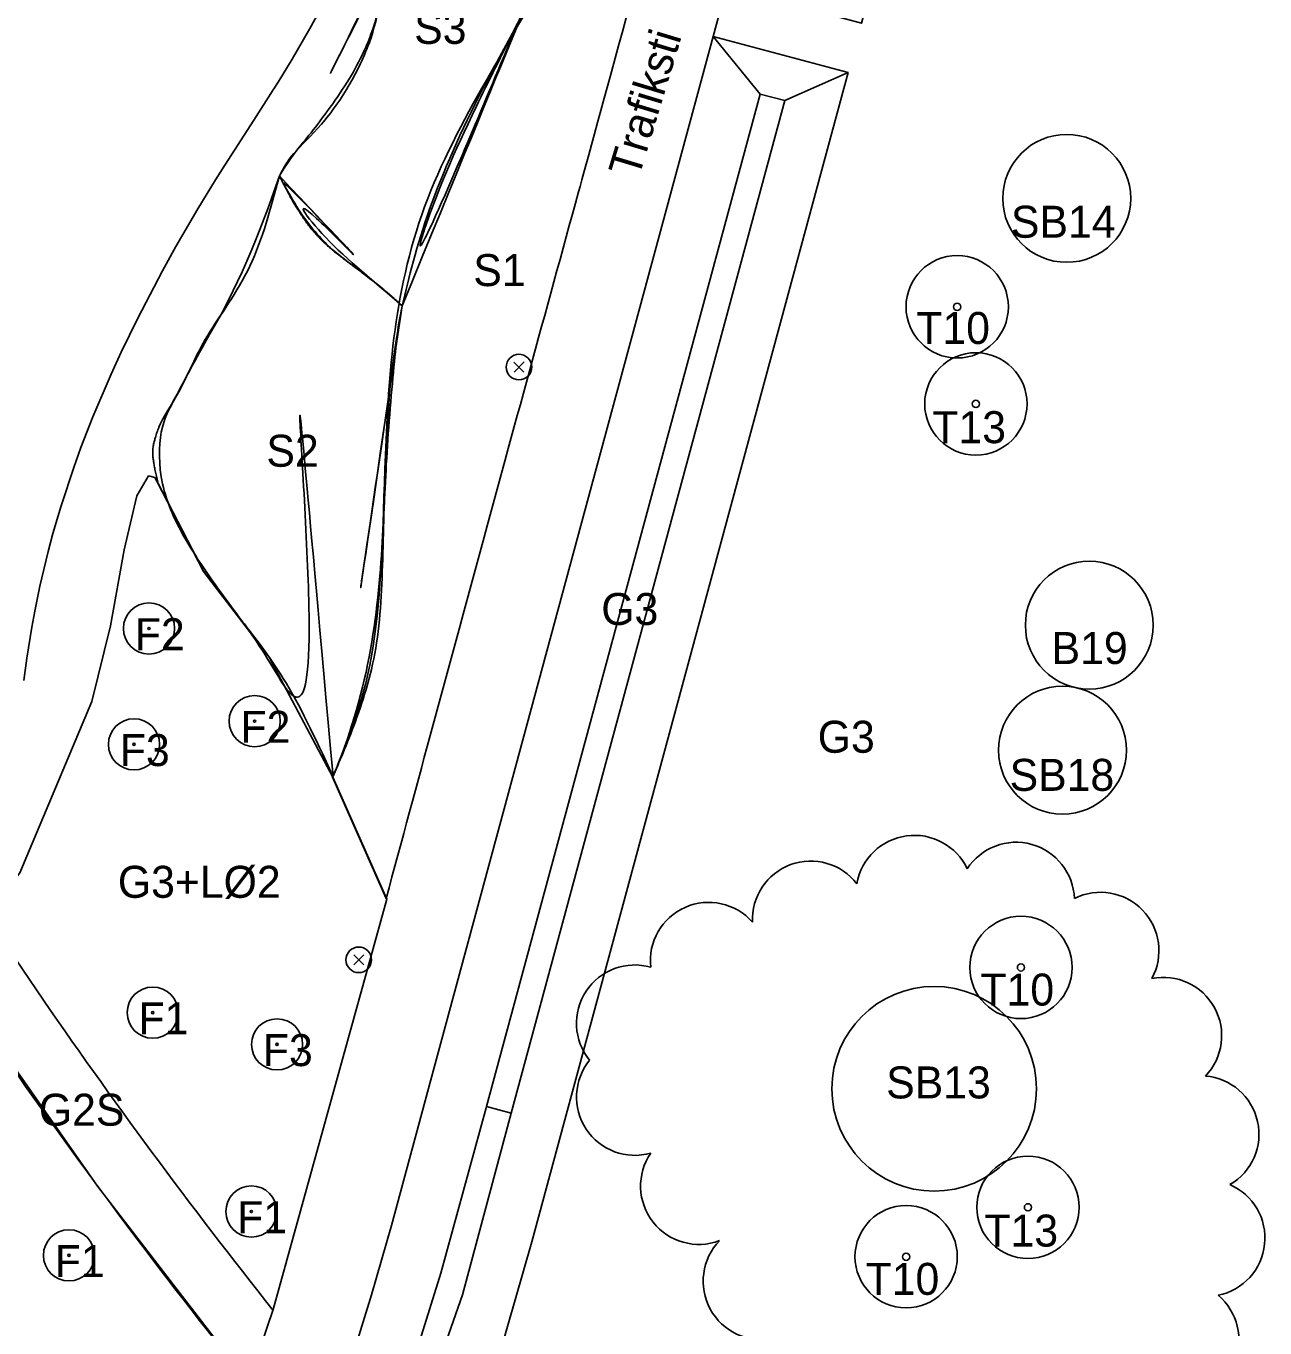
# Model space of a CAD drawing. Extents: x 0 to 512122, y 0 to 6212554.
# Drawn here: x 511701.5 to 511749.9, y 6211598.5 to 6211649.4 of the extents above; entities that cross this region are included whole.
import ezdxf

# ---------------------------------------------------------------- set-up
doc = ezdxf.new("R2010")
doc.units = 0
for name, color, linetype in [('_lights', 7, 'Continuous'), ('_LØ2', 7, 'Continuous'), ('_ny fruit trees', 7, 'Continuous'), ('_Paths', 7, 'Continuous'), ('_S1_rabarber', 7, 'Continuous'), ('_S2_skovjorbær', 7, 'Continuous'), ('_S3_Mynte', 7, 'Continuous'), ('Bassin - bottom', 7, 'Continuous'), ('Clouds', 7, 'Continuous'), ('L40 jord udlagt muld og grøft', 7, 'Continuous'), ('Skel', 7, 'Continuous'), ('TV_U_AFM_Symbl_Gul', 7, 'Continuous'), ('TV_U_LYS_Mastenummer', 7, 'Continuous'), ('TV_U_LYS_Nyx330-Trafiksti-x2', 7, 'Continuous')]:
    doc.layers.add(name, color=color, linetype=linetype)

# ---------------------------------------------------------------- blocks, each defined once
blk = doc.blocks.new('SOLITAIRE TREES')
at = {"layer": 'Skel'}
for radius in [2, 0.141]:
    blk.add_circle((0, 0), radius, dxfattribs=at)

msp = doc.modelspace()

# ---------------------------------------------------------------- linework, layer by layer
at = {"layer": '_lights'}
for p, q in [((511720.531, 6211636.26), (511720.925, 6211635.866)), ((511720.929, 6211636.264), (511720.535, 6211635.87)), ((511714.267, 6211613.092), (511714.661, 6211612.698)), ((511714.665, 6211613.096), (511714.271, 6211612.702))]:
    msp.add_line(p, q, dxfattribs=at)
for centre, start, end in [((511720.728, 6211636.063), 315.5636, 315), ((511720.728, 6211636.063), 315, 315.5636), ((511714.464, 6211612.895), 315.5636, 315), ((511714.464, 6211612.895), 315, 315.5636)]:
    msp.add_arc(centre, 0.5, start, end, dxfattribs=at)
at = {"layer": '_LØ2'}
msp.add_lwpolyline([(511711.121, 6211599.231), (511715.557, 6211615.262), (511713.457, 6211620.03), (511710.963, 6211624.728), (511708.398, 6211628.07), (511706.573, 6211631.603), (511706.496, 6211631.752), (511706.246, 6211631.811), (511705.782, 6211631.027), (511705.291, 6211628.924), (511704.763, 6211625.953), (511704.035, 6211622.995), (511702.625, 6211619.644), (511701.216, 6211616.293), (511699.914, 6211614.606), (511697.985, 6211612.99), (511704.249, 6211604.056), (511710.152, 6211596.395)], close=True, dxfattribs=at)
at = {"layer": '_ny fruit trees'}
for centre, radius in [((511706.263, 6211625.847), 1), ((511706.263, 6211625.847), 0.0426), ((511710.394, 6211622.225), 1), ((511705.678, 6211621.316), 1), ((511710.394, 6211622.225), 0.0426), ((511705.678, 6211621.316), 0.0426), ((511706.41, 6211610.833), 1), ((511706.41, 6211610.833), 0.0426), ((511711.271, 6211609.59), 1), ((511711.271, 6211609.59), 0.0426), ((511710.267, 6211603.058), 1), ((511710.267, 6211603.058), 0.0426), ((511703.133, 6211601.345), 1), ((511703.133, 6211601.345), 0.0426)]:
    msp.add_circle(centre, radius, dxfattribs=at)
at = {"layer": '_Paths'}
for radius, end in [(226.178, 218.4293), (228.678, 218.83127)]:
    msp.add_arc((511888.3, 6211739.773), radius, 210.53527, end, dxfattribs=at)
at = {"layer": '_S1_rabarber'}
msp.add_line((511713.443, 6211620.033), (511715.535, 6211615.293), dxfattribs=at)
msp.add_line((511713.443, 6211620.033), (511715.535, 6211615.293), dxfattribs=at)
for points in [[(511725.352, 6211662.529), (511725.349, 6211662.493), (511725.092, 6211659.458), (511722.57, 6211651.867), (511715.885, 6211642.179), (511715.448, 6211631.484), (511715.258, 6211624.37), (511713.955, 6211621.257), (511713.443, 6211620.033)], [(511725.352, 6211662.529), (511725.349, 6211662.493), (511725.092, 6211659.458), (511722.57, 6211651.867), (511715.885, 6211642.179), (511715.448, 6211631.484), (511715.258, 6211624.37), (511713.955, 6211621.257), (511713.443, 6211620.033)], [(511723.059, 6211642.917), (511723.333, 6211643.917), (511724.935, 6211649.766), (511726.53, 6211655.617), (511727.845, 6211660.47)], [(511723.059, 6211642.917), (511723.333, 6211643.917), (511724.935, 6211649.766), (511726.53, 6211655.617), (511727.845, 6211660.47)], [(511715.535, 6211615.293), (511716.748, 6211619.778), (511719.24, 6211628.991), (511721.765, 6211638.194), (511723.059, 6211642.917)], [(511715.535, 6211615.293), (511716.748, 6211619.778), (511719.24, 6211628.991), (511721.765, 6211638.194), (511723.059, 6211642.917)]]:
    msp.add_open_spline(points, degree=3, dxfattribs=at)
at = {"layer": '_S2_skovjorbær'}
msp.add_line((511706.622, 6211631.508), (511708.351, 6211628.16), dxfattribs=at)
for points, degree in [([(511711.36, 6211643.536), (511710.107, 6211639.844), (511708.285, 6211636.794), (511707.235, 6211634.736), (511706.654, 6211633.719), (511706.623, 6211631.504), (511707.621, 6211629.259), (511709.586, 6211626.538), (511710.963, 6211624.728), (511713.458, 6211620.071), (511711.36, 6211643.536), (511713.458, 6211620.071)], 3), ([(511711.36, 6211643.536), (511710.107, 6211639.844), (511708.285, 6211636.794), (511707.235, 6211634.736), (511706.654, 6211633.719), (511706.623, 6211631.504), (511707.621, 6211629.259), (511709.586, 6211626.538), (511710.963, 6211624.728), (511713.458, 6211620.071), (511711.36, 6211643.536), (511713.458, 6211620.071)], 3), ([(511711.36, 6211643.536), (511711.024, 6211642.267), (511710.383, 6211639.841), (511708.362, 6211637.216), (511707.493, 6211635.036), (511706.797, 6211634.077), (511706.654, 6211633.719)], 3), ([(511716.159, 6211638.46), (511715.123, 6211639.357), (511712.858, 6211641.188), (511711.36, 6211643.536), (511716.159, 6211638.46), (511711.36, 6211643.536)], 3), ([(511716.159, 6211638.46), (511715.123, 6211639.357), (511712.858, 6211641.188), (511711.36, 6211643.536), (511716.159, 6211638.46), (511711.36, 6211643.536)], 3), ([(511712.097, 6211642.206), (511711.886, 6211642.536), (511711.645, 6211642.984), (511711.413, 6211643.434), (511711.36, 6211643.536)], 3), ([(511712.129, 6211642.155), (511712.118, 6211642.172), (511712.108, 6211642.189), (511712.097, 6211642.206)], 2), ([(511712.858, 6211641.188), (511712.585, 6211641.483), (511712.347, 6211641.81), (511712.129, 6211642.155)], 2), ([(511713.399, 6211640.674), (511713.208, 6211640.836), (511713.026, 6211641.006), (511712.858, 6211641.188)], 2), ([(511713.434, 6211640.645), (511713.422, 6211640.654), (511713.411, 6211640.664), (511713.399, 6211640.674)], 2), ([(511714.234, 6211640.025), (511713.961, 6211640.226), (511713.69, 6211640.429), (511713.434, 6211640.645)], 2), ([(511714.905, 6211639.519), (511714.682, 6211639.689), (511714.458, 6211639.856), (511714.234, 6211640.025)], 2), ([(511715.354, 6211639.168), (511715.207, 6211639.288), (511715.056, 6211639.404), (511714.905, 6211639.519)], 2), ([(511715.986, 6211638.616), (511715.778, 6211638.803), (511715.569, 6211638.988), (511715.354, 6211639.168)], 2), ([(511716.159, 6211638.46), (511716.102, 6211638.512), (511716.044, 6211638.564), (511715.986, 6211638.616)], 2), ([(511713.458, 6211620.071), (511714.091, 6211621.562), (511715.044, 6211624.75), (511715.425, 6211629.426), (511715.54, 6211632.832), (511715.927, 6211637.149), (511716.159, 6211638.46), (511713.458, 6211620.071), (511716.159, 6211638.46)], 3), ([(511713.458, 6211620.071), (511714.091, 6211621.562), (511715.044, 6211624.75), (511715.425, 6211629.426), (511715.54, 6211632.832), (511715.927, 6211637.149), (511716.159, 6211638.46), (511713.458, 6211620.071), (511716.159, 6211638.46)], 3), ([(511713.458, 6211620.071), (511713.675, 6211620.565), (511714.338, 6211622.074), (511715.307, 6211625.167), (511715.412, 6211629.004), (511715.53, 6211633.138), (511715.731, 6211636.167), (511716.078, 6211638.023), (511716.159, 6211638.46)], 3), ([(511706.654, 6211633.719), (511706.383, 6211633.043), (511706.437, 6211632.242), (511706.622, 6211631.508)], 2), ([(511708.351, 6211628.16), (511708.745, 6211627.608), (511709.164, 6211627.071), (511709.586, 6211626.538)], 2), ([(511709.586, 6211626.538), (511710.058, 6211625.942), (511711.639, 6211623.975), (511712.709, 6211621.677), (511713.458, 6211620.071)], 3)]:
    msp.add_open_spline(points, degree=degree, dxfattribs=at)
at = {"layer": '_S3_Mynte'}
for points, degree in [([(511724.952, 6211659.807), (511724.306, 6211657.401), (511722.522, 6211653.033), (511718.71, 6211645.702), (511717.032, 6211641.695), (511716.159, 6211638.46), (511724.952, 6211659.807), (511716.159, 6211638.46)], 3), ([(511716.159, 6211638.46), (511716.422, 6211639.547), (511717.026, 6211642.044), (511719.194, 6211646.93), (511722.109, 6211651.909), (511724.172, 6211656.666), (511724.752, 6211659), (511724.952, 6211659.807)], 3), ([(511711.36, 6211643.536), (511711.891, 6211644.398), (511712.422, 6211644.945), (511714.272, 6211647.442), (511715.067, 6211649.303), (511715.306, 6211650.373), (511715.73, 6211652.007), (511716.355, 6211653.575), (511711.36, 6211643.536), (511716.355, 6211653.575)], 3), ([(511716.355, 6211653.575), (511716.131, 6211653.058), (511715.683, 6211652.023), (511715.335, 6211650.569), (511715.041, 6211648.99), (511714.161, 6211647.086), (511713.013, 6211645.467), (511711.799, 6211644.365), (511711.52, 6211643.837), (511711.36, 6211643.536)], 3), ([(511716.159, 6211638.46), (511715.986, 6211638.616), (511715.44, 6211639.097), (511714.905, 6211639.519), (511713.759, 6211640.386), (511713.399, 6211640.674), (511712.76, 6211641.315), (511712.097, 6211642.206), (511711.519, 6211643.229), (511711.36, 6211643.536), (511716.159, 6211638.46), (511711.36, 6211643.536)], 3), ([(511711.36, 6211643.536), (511711.606, 6211643.066), (511711.851, 6211642.596), (511712.129, 6211642.155)], 2), ([(511712.129, 6211642.155), (511712.32, 6211641.861), (511712.53, 6211641.58), (511712.76, 6211641.315)], 2), ([(511712.76, 6211641.315), (511712.958, 6211641.087), (511713.17, 6211640.87), (511713.399, 6211640.674)], 2), ([(511713.399, 6211640.674), (511713.411, 6211640.664), (511713.422, 6211640.654), (511713.434, 6211640.645)], 2), ([(511713.434, 6211640.645), (511713.54, 6211640.556), (511713.649, 6211640.471), (511713.759, 6211640.386)], 2), ([(511713.759, 6211640.386), (511713.917, 6211640.265), (511714.075, 6211640.145), (511714.234, 6211640.025)], 2), ([(511714.234, 6211640.025), (511714.533, 6211639.805), (511714.834, 6211639.587), (511715.123, 6211639.357)], 2), ([(511715.123, 6211639.357), (511715.201, 6211639.295), (511715.278, 6211639.232), (511715.354, 6211639.168)], 2), ([(511715.354, 6211639.168), (511715.383, 6211639.145), (511715.412, 6211639.121), (511715.44, 6211639.097)], 2), ([(511715.44, 6211639.097), (511715.624, 6211638.944), (511715.801, 6211638.783), (511715.978, 6211638.623)], 2), ([(511715.978, 6211638.623), (511716.039, 6211638.569), (511716.099, 6211638.514), (511716.159, 6211638.46)], 2)]:
    msp.add_open_spline(points, degree=degree, dxfattribs=at)
at = {"layer": 'Bassin - bottom'}
msp.add_lwpolyline([(511713.191, 6211650.47), (511712.557, 6211649.297), (511711.859, 6211648.101), (511711.494, 6211647.502), (511711.308, 6211647.203), (511711.12, 6211646.904), (511710.361, 6211645.716), (511709.602, 6211644.54), (511709.23, 6211643.957), (511709.138, 6211643.812), (511709.047, 6211643.668), (511708.867, 6211643.38), (511708.174, 6211642.245), (511707.317, 6211640.775), (511706.787, 6211639.822), (511705.821, 6211637.978), (511705.175, 6211636.649), (511704.779, 6211635.787), (511704.069, 6211634.12), (511703.603, 6211632.919), (511703.321, 6211632.141), (511702.825, 6211630.638), (511702.507, 6211629.556), (511702.319, 6211628.855), (511701.995, 6211627.502), (511701.794, 6211626.529), (511701.677, 6211625.9), (511701.483, 6211624.686), (511701.366, 6211623.816)], dxfattribs=at)
at = {"layer": 'Clouds'}
for centre, radius, start, end in [((511736.19, 6211615.481), 2.281, 25.2077, 170.2077), ((511740.166, 6211615.211), 2.28, 2.0157, 147.0157), ((511732.137, 6211614.475), 2.281, 37.6761, 182.6761), ((511728.146, 6211612.861), 2.281, 41.3523, 186.3523), ((511743.466, 6211613.252), 2.282, 331.608, 116.608), ((511725.258, 6211610.415), 2.28, 74.1952, 219.1952), ((511745.921, 6211609.93), 2.281, 316.3178, 101.3178), ((511725.26, 6211607.534), 2.281, 140.8408, 285.8408), ((511747.379, 6211606.082), 2.281, 300.1916, 85.1916), ((511727.765, 6211604.054), 2.281, 145.6596, 290.6596), ((511747.614, 6211602.02), 2.281, 281.4375, 66.4375), ((511730.21, 6211600.334), 2.281, 135.9748, 280.9748), ((511746.596, 6211598.041), 2.281, 264.8625, 49.8625)]:
    msp.add_arc(centre, radius, start, end, dxfattribs=at)
at = {"layer": 'L40 jord udlagt muld og grøft'}
msp.add_lwpolyline([(511719.958, 6211597.433), (511721.235, 6211601.868), (511723.218, 6211609.192), (511730.526, 6211636.221), (511733.595, 6211647.574), (511728.319, 6211648.988), (511728.841, 6211650.918), (511734.117, 6211649.504), (511739.91, 6211670.932), (511734.664, 6211672.473), (511728.315, 6211648.989), (511717.418, 6211608.688), (511715.74, 6211602.51), (511714.965, 6211599.808), (511714.305, 6211597.689)], dxfattribs=at)
for points in [[(511728.315, 6211648.989), (511730.155, 6211646.735), (511731.121, 6211646.477), (511733.595, 6211647.574)], [(511730.155, 6211646.735), (511731.121, 6211646.477), (511720.42, 6211606.898), (511719.454, 6211607.157)], [(511704.816, 6211575.161), (511704.095, 6211575.854), (511707.325, 6211579.538), (511710.411, 6211583.817), (511713.1, 6211588.498), (511714.705, 6211591.954), (511716.026, 6211595.388), (511717.675, 6211600.653), (511719.44, 6211607.105), (511719.454, 6211607.157), (511720.42, 6211606.898), (511718.52, 6211599.808), (511717.276, 6211596.237), (511715.672, 6211591.632), (511713.465, 6211587.061), (511711.085, 6211583.038), (511708.244, 6211579.086)]]:
    msp.add_lwpolyline(points, close=True, dxfattribs=at)
at = {"layer": 'TV_U_LYS_Mastenummer'}
for centre, radius in [((511742.144, 6211642.657), 2.5), ((511743.026, 6211625.977), 2.5), ((511743.026, 6211625.977), 2.5), ((511741.978, 6211621.088), 2.5), ((511741.978, 6211621.088), 2.5), ((511736.962, 6211607.856), 4), ((511736.962, 6211607.856), 4)]:
    msp.add_circle(centre, radius, dxfattribs=at)
at = {"layer": 'TV_U_LYS_Nyx330-Trafiksti-x2'}
msp.add_lwpolyline([(511701.366, 6211623.816), (511701.483, 6211624.686), (511701.677, 6211625.9), (511701.794, 6211626.529), (511701.995, 6211627.502), (511702.319, 6211628.855), (511702.507, 6211629.556), (511702.825, 6211630.638), (511703.321, 6211632.141), (511703.603, 6211632.919), (511704.069, 6211634.12), (511704.779, 6211635.787), (511705.175, 6211636.649), (511705.821, 6211637.978), (511706.787, 6211639.822), (511707.317, 6211640.775), (511708.174, 6211642.245), (511708.867, 6211643.38), (511709.047, 6211643.668), (511709.138, 6211643.812), (511709.23, 6211643.957), (511709.602, 6211644.54), (511710.361, 6211645.716), (511711.12, 6211646.904), (511711.308, 6211647.203), (511711.494, 6211647.502), (511711.859, 6211648.101), (511712.557, 6211649.297), (511713.191, 6211650.47)], dxfattribs=at)

# ---------------------------------------------------------------- block references
at = {"layer": 'Skel'}
for p in [(511737.862, 6211638.419), (511738.592, 6211634.624), (511740.355, 6211612.598), (511740.629, 6211603.223), (511735.866, 6211601.291)]:
    msp.add_blockref('SOLITAIRE TREES', p, dxfattribs=at)

# ---------------------------------------------------------------- texts
at = {"layer": 'TV_U_AFM_Symbl_Gul'}
for s, p in [('S3', (511716.632, 6211648.695)), ('SB14', (511739.964, 6211641.118)), ('S1', (511718.944, 6211639.228)), ('T10', (511736.262, 6211636.966)), ('T13', (511736.889, 6211633.089)), ('S2', (511710.854, 6211632.168)), ('G3', (511723.946, 6211625.982)), ('F2', (511705.709, 6211624.998)), ('B19', (511741.554, 6211624.458)), ('F2', (511709.84, 6211621.377)), ('G3', (511732.41, 6211620.989)), ('F3', (511705.123, 6211620.468)), ('SB18', (511739.912, 6211619.5)), ('G3+LØ2', (511705.046, 6211615.32)), ('T10', (511738.77, 6211611.108)), ('F1', (511705.856, 6211609.985)), ('F3', (511710.717, 6211608.742)), ('SB13', (511735.086, 6211607.479)), ('G2S', (511701.957, 6211606.412)), ('F1', (511709.712, 6211602.21)), ('T13', (511738.926, 6211601.688)), ('F1', (511702.578, 6211600.497)), ('T10', (511734.281, 6211599.801))]:
    msp.add_text(s, height=1.25, dxfattribs=at).set_placement(p)
msp.add_text('Trafiksti', height=1.25, rotation=73.1756, dxfattribs=at).set_placement((511725.407, 6211643.407))

doc.saveas('drawing.dxf')
